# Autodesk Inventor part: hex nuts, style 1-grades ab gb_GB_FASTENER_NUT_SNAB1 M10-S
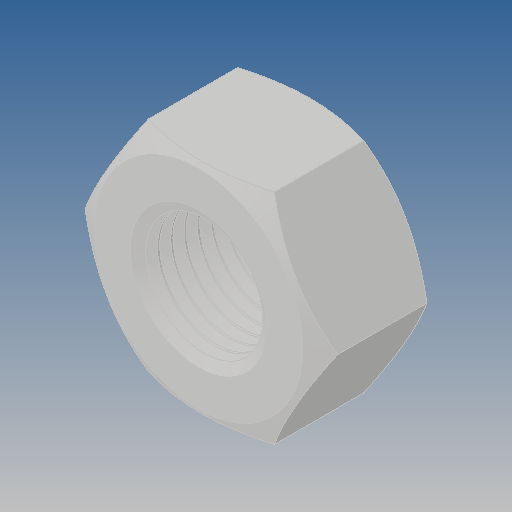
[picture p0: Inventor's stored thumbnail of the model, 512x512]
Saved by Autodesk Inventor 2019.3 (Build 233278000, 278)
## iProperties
Created: 2017-08
Part Number: hex nuts, style 1-grades ab gb_GB_FASTENER_NUT_SNAB1 M10-S
Material: Ogólny
Document SubType Name: Modeling
Designer: Admin
Density: 1 g/cm^3
Appearance: Domyślna
Author: Admin
Revision Number: ÈÎºÎ
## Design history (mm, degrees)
feature "ÊäÈë1"
node "Bryła1"
